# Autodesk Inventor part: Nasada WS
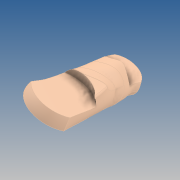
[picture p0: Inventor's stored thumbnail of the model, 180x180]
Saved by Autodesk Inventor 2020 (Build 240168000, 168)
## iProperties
Created: 2019-10
Part Number: Nasada WS
Material: GFRP
Document SubType Name: Modeling
Designer: yello
Density: 1.75 g/cm^3
Appearance: Default
Author: yello
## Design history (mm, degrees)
feature "Nasada WS"
body "Solid1"
